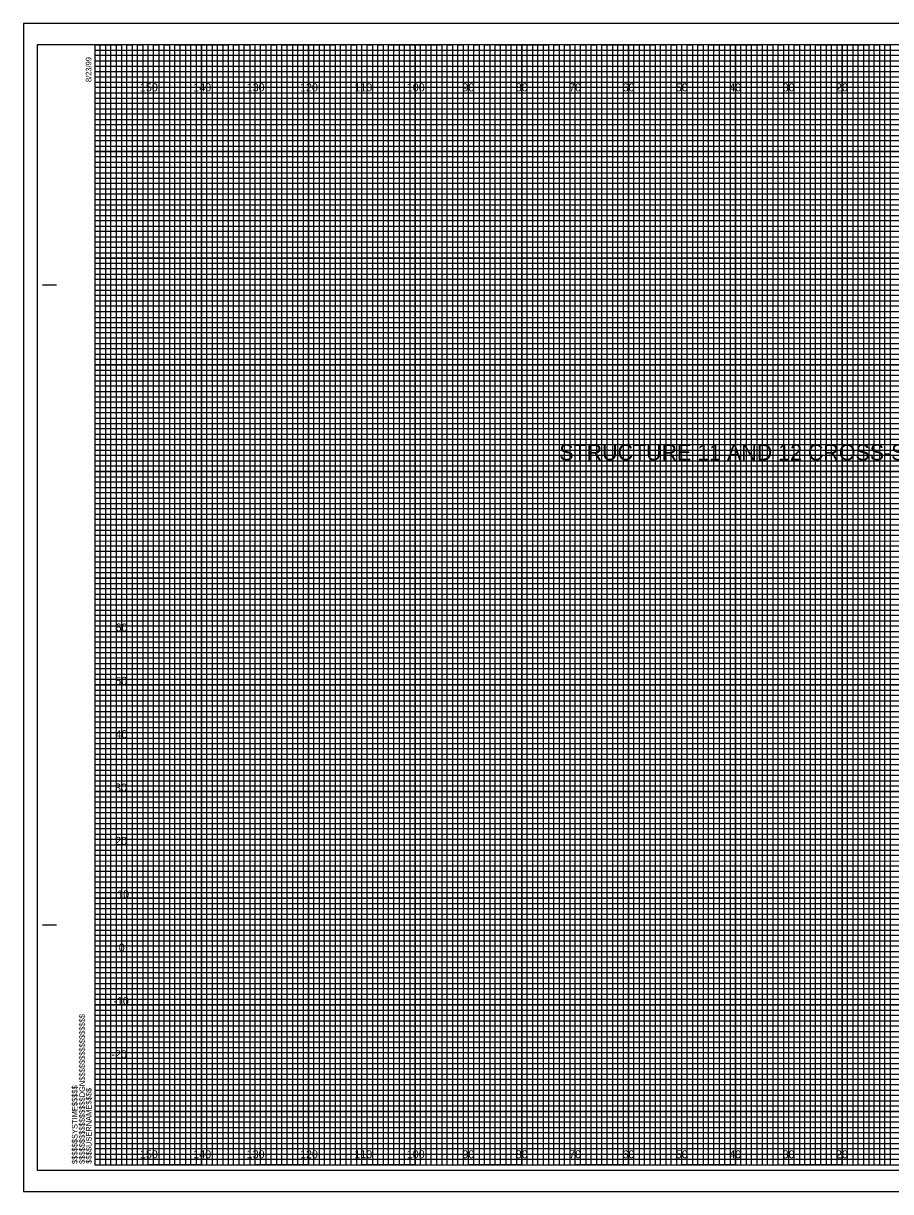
# Model space of a CAD drawing. Extents: x -13 to 886, y -5 to 434.
# Drawn here: x -13.4 to 149.1, y 215 to 434 of the extents above; entities that cross this region are included whole.
import ezdxf

# ---------------------------------------------------------------- set-up
doc = ezdxf.new("R2010")
doc.units = 0
for name, color, linetype in [('Prop Road Sect_ Boring - Header Labels from Geopak', 7, 'Continuous'), ('Prop XS Elevation Labels', 7, 'Continuous'), ('Prop XS Offset Labels', 7, 'Continuous'), ('Sheet Cross Section CELL', 7, 'Continuous'), ('Sheet Cross Section Grid Major CELL', 7, 'Continuous'), ('Sheet Cross Section Grid Middle CELL', 7, 'Continuous'), ('Sheet Cross Section Grid Minor 1 CELL', 7, 'Continuous'), ('Sheet Cross Section Grid Minor 2 CELL', 7, 'Continuous'), ('Sheet Cutting Line CELL', 7, 'Continuous'), ('Sheet DOT Grid CELL', 7, 'Continuous'), ('Sheet Plot Border Inside CELL', 7, 'Continuous'), ('Sheet Plot Border Outside CELL', 7, 'Continuous')]:
    doc.layers.add(name, color=color, linetype=linetype)

msp = doc.modelspace()

# ---------------------------------------------------------------- linework, layer by layer
at = {"layer": 'Sheet Cross Section CELL'}
for p, q in [((-9.8, 385), (-7.3, 385)), ((-9.7, 385), (-7.2, 385)), ((-9.8, 265), (-7.3, 265)), ((-9.7, 265), (-7.2, 265)), ((0, 220), (0, 220)), ((0, 220), (0, 220)), ((0, 220), (0, 220)), ((0, 220), (0, 220)), ((0, 220), (0, 220)), ((0, 220), (0, 220)), ((0, 220), (0, 220))]:
    msp.add_line(p, q, dxfattribs=at)
msp.add_lwpolyline([(320, 430), (0, 430), (0, 220), (320, 220)], close=True, dxfattribs=at)
at = {"layer": 'Sheet Cross Section Grid Major CELL'}
for p, q in [((10, 430), (0, 430)), ((10, 220), (10, 430)), ((30, 430), (20, 430)), ((20, 430), (20, 220)), ((30, 220), (30, 430)), ((50, 430), (40, 430)), ((40, 430), (40, 220)), ((50, 220), (50, 430)), ((70, 430), (60, 430)), ((60, 430), (60, 220)), ((70, 220), (70, 430)), ((90, 430), (80, 430)), ((80, 430), (80, 220)), ((90, 220), (90, 430)), ((110, 430), (100, 430)), ((100, 430), (100, 220)), ((110, 220), (110, 430)), ((130, 430), (120, 430)), ((120, 430), (120, 220)), ((130, 220), (130, 430)), ((150, 430), (140, 430)), ((140, 430), (140, 220)), ((20, 220), (10, 220)), ((40, 220), (30, 220)), ((60, 220), (50, 220)), ((80, 220), (70, 220)), ((100, 220), (90, 220)), ((120, 220), (110, 220)), ((140, 220), (130, 220))]:
    msp.add_line(p, q, dxfattribs=at)
for points in [[(0, 420), (320, 420), (320, 410), (0, 410)], [(0, 400), (320, 400), (320, 390), (0, 390)], [(0, 380), (320, 380), (320, 370), (0, 370)], [(0, 360), (320, 360), (320, 350), (0, 350)], [(0, 340), (320, 340), (320, 330), (0, 330)], [(0, 320), (320, 320), (320, 310), (0, 310)], [(0, 300), (320, 300), (320, 290), (0, 290)], [(0, 280), (320, 280), (320, 270), (0, 270)], [(0, 260), (320, 260), (320, 250), (0, 250)], [(0, 240), (320, 240), (320, 230), (0, 230)]]:
    msp.add_lwpolyline(points, dxfattribs=at)
at = {"layer": 'Sheet Cross Section Grid Middle CELL'}
for points in [[(0, 430), (5, 430), (5, 220), (15, 220), (15, 430), (25, 430), (25, 220), (35, 220), (35, 430), (45, 430), (45, 220), (55, 220), (55, 430), (65, 430), (65, 220), (75, 220), (75, 430), (85, 430), (85, 220), (95, 220), (95, 430), (105, 430), (105, 220), (115, 220), (115, 430), (125, 430), (125, 220), (135, 220), (135, 430), (145, 430), (145, 220), (155, 220)], [(0, 425), (275, 425)], [(0, 405), (320, 405), (320, 415), (0, 415)], [(0, 385), (320, 385), (320, 395), (0, 395)], [(0, 365), (320, 365), (320, 375), (0, 375)], [(0, 345), (320, 345), (320, 355), (0, 355)], [(0, 325), (320, 325), (320, 335), (0, 335)], [(0, 305), (320, 305), (320, 315), (0, 315)], [(0, 285), (320, 285), (320, 295), (0, 295)], [(0, 265), (320, 265), (320, 275), (0, 275)], [(0, 245), (320, 245), (320, 255), (0, 255)], [(0, 225), (320, 225), (320, 235), (0, 235)]]:
    msp.add_lwpolyline(points, dxfattribs=at)
at = {"layer": 'Sheet Cross Section Grid Minor 1 CELL'}
for p, q in [((0, 429), (260, 429)), ((260, 427.98), (0, 427.98)), ((0, 427.98), (0, 427)), ((0, 427), (260, 427)), ((260, 425.89), (0, 425.89)), ((0, 425.89), (0, 424)), ((0, 424), (320, 424))]:
    msp.add_line(p, q, dxfattribs=at)
for points in [[(0, 423), (270, 423), (320, 423), (320, 422), (0, 422)], [(0, 421), (320, 421), (320, 419), (0, 419)], [(0, 418), (320, 418), (320, 417), (0, 416.98)], [(0, 416), (320, 416), (320, 414), (0, 414)], [(0, 413), (320, 413), (320, 412), (0, 412)], [(0, 411), (320, 411), (320, 409), (0, 409)], [(0, 408), (320, 408), (320, 407), (0, 407)], [(0, 406), (320, 406), (320, 404), (0, 404)], [(0, 403), (320, 403), (320, 402), (0, 402)], [(0, 401), (320, 401), (320, 399), (0, 399)], [(0, 398), (320, 398), (320, 397), (0, 397)], [(0, 396), (320, 396), (320, 393.95), (320, 393), (320, 392), (0, 392)], [(0, 394), (320, 394), (320, 393), (0, 393)], [(0, 391), (320, 391), (320, 389), (0, 389.03)], [(0, 389.03), (320, 389), (320, 388), (0, 388)], [(0, 387), (320, 387), (320, 386), (0, 386)], [(0, 384), (320, 384), (320, 383), (0, 383)], [(0, 382), (320, 382), (320, 381), (0, 381)], [(-0.07, 378.89), (320, 378.89), (320, 377.88), (-0.07, 377.88)], [(0, 377), (320, 377), (320, 376), (0, 376)], [(0, 374), (320, 374), (320, 373), (0, 373)], [(0, 372), (320, 372), (320, 371), (0, 371)], [(0, 369), (320, 369), (320, 368), (0, 368)], [(0, 367), (320, 367), (320, 366), (0, 366)], [(0, 364), (320, 364), (320, 363), (0, 363)], [(0, 362), (320, 362), (320, 361), (0, 361)], [(0, 359), (320, 359), (319.99, 357.98), (0, 358)], [(0, 357), (320, 357), (320, 356), (0, 356)], [(0, 354), (320, 354), (320, 353), (0, 353)], [(0, 352), (320, 352), (320, 351), (0, 351)], [(0, 349), (320, 349), (320, 348), (0, 348)], [(0, 347), (320, 347), (320, 346), (0, 346)], [(0, 344), (320, 344), (320, 343), (0, 343)], [(0, 342), (320, 342), (320, 341), (0, 341)], [(0, 339), (320, 339), (320, 338), (0, 338)], [(0, 336.99), (320.07, 336.91), (320, 336), (0, 336)], [(0, 334), (320, 334), (320, 333), (0, 333)], [(0, 332), (320, 332), (320, 331), (0, 331)], [(0, 329), (320, 329), (320, 328), (0, 328)], [(0, 327), (320, 327), (320, 326), (0, 326)], [(0, 324), (320, 324), (320, 323), (0, 323)], [(0, 322), (320, 322), (320, 321), (0, 321)], [(0, 319), (320, 319), (320, 318), (0, 318)], [(0, 317), (320, 317), (320, 316), (0, 316)], [(0, 314), (320, 314), (320, 313), (0, 313)], [(0, 312), (320, 312), (320, 311), (0, 311)], [(0, 309), (320, 309), (320, 308), (0, 308)], [(0, 307), (320, 307), (320, 306), (0, 306)], [(0, 304), (320, 304), (320, 303), (0, 303)], [(0, 302), (320, 302), (320, 301), (0, 301)], [(0, 299), (320, 299), (319.99, 297.98), (0, 298)], [(0, 297), (320, 297), (320, 296), (0, 296)], [(0, 294), (320, 294), (320, 293), (0, 293)], [(0, 292), (320, 292), (320, 291), (0, 291)], [(0, 289), (320, 289), (320, 288), (0, 288)], [(0, 287), (320, 287), (320, 286), (0, 286)], [(0, 284), (320, 284), (320, 283), (0, 283)], [(0, 282), (320, 282), (320, 281), (0, 281)], [(0, 279), (320, 279), (320, 278), (0, 278)], [(0, 276.99), (320.07, 276.91), (320, 276), (0, 276)], [(0, 274), (320, 274), (320, 273), (0, 273)], [(0, 272), (320, 272), (320, 271), (0, 271)], [(0, 269), (320, 269), (320, 268), (0, 268)], [(0, 267), (320, 267), (320, 266), (0, 266)], [(0, 264), (320, 264), (320, 263), (0, 263)], [(0, 262), (320, 262), (320, 261), (0, 261)], [(0, 259), (320, 259), (320, 258), (0, 258)], [(0, 257), (320, 257), (320, 256), (0, 256)], [(0, 254), (320, 254), (320, 253), (0, 253)], [(0, 252), (320, 252), (320, 251), (0, 251)], [(0, 249), (320, 249), (320, 248), (0, 248)], [(0, 247), (320, 247), (320, 246), (0, 246)], [(0, 244), (320, 244), (320, 243), (0, 243)], [(0, 242), (320, 242), (320, 241), (0, 241)], [(0, 239), (320, 239), (320, 238), (0, 238)], [(0, 237), (320, 237), (320, 236), (0, 236)], [(0, 234), (320, 234), (320, 233), (0, 233)], [(0, 232), (320, 232), (320, 231), (0, 231)], [(0, 229), (320, 229), (320, 228), (0, 228)], [(0, 227), (320, 227), (320, 226), (0, 226)], [(0, 224), (320, 224), (320, 223), (0, 223)], [(0, 222), (320, 222), (320, 221), (0, 221)]]:
    msp.add_lwpolyline(points, dxfattribs=at)
at = {"layer": 'Sheet Cross Section Grid Minor 2 CELL'}
for points in [[(0, 220), (1, 220), (1, 430), (2, 430), (2, 220)], [(2, 220), (3, 220), (3, 430), (4, 430), (4, 220)], [(5, 220), (6, 220), (6, 430), (7, 430), (7, 220)], [(7, 220), (8, 220), (8, 430), (9, 430), (9, 220)], [(10, 220), (11, 220), (11, 430), (12, 430), (12, 220)], [(12, 220), (13, 220), (13, 430), (14, 430), (14, 220)], [(15, 220), (16, 220), (16, 430), (17, 430), (17, 220)], [(17, 220), (18, 220), (18, 430), (19, 430), (19, 220)], [(20, 220), (21, 220), (21, 430), (22, 430), (22, 220)], [(22, 220), (23, 220), (23, 430), (24, 430), (24, 220)], [(25, 220), (26, 220), (26, 430), (27, 430), (27, 220)], [(27, 220), (28, 220), (28, 430), (29, 430), (29, 220)], [(30, 220), (31, 220), (31, 430), (32, 430), (32, 220)], [(32, 220), (33, 220), (33, 430), (34, 430), (34, 220)], [(35, 220), (36, 220), (36, 430), (37, 430), (37, 220)], [(37, 220), (38, 220), (38, 430), (39, 430), (39, 220)], [(40, 220), (41, 220), (41, 430), (42, 430), (42, 220)], [(42, 220), (43, 220), (43, 430), (44, 430), (44, 220)], [(45, 220), (46, 220), (46, 430), (47, 430), (47, 220)], [(47, 220), (48, 220), (48, 430), (49, 430), (49, 220)], [(50, 220), (51, 220), (51, 430), (52, 430), (52, 220)], [(52, 220), (53, 220), (53, 430), (54, 430), (54, 220)], [(55, 220), (56, 220), (56, 430), (57, 430), (57, 220)], [(57, 220), (58, 220), (58, 430), (59, 430), (59, 220)], [(60, 220), (61, 220), (61, 430), (62, 430), (62, 220)], [(62, 220), (63, 220), (63, 430), (64, 430), (64, 220)], [(65, 220), (66, 220), (66, 430), (67, 430), (67, 220)], [(67, 220), (68, 220), (68, 430), (69, 430), (69, 220)], [(70, 220), (71, 220), (71, 430), (72, 430), (72, 220)], [(72, 220), (73, 220), (73, 430), (74, 430), (74, 220)], [(75, 220), (76, 220), (76, 430), (77, 430), (77, 220)], [(77, 220), (78, 220), (78, 430), (79, 430), (79, 220)], [(80, 220), (81, 220), (81, 430), (82, 430), (82, 220)], [(82, 220), (83, 220), (83, 430), (84, 430), (84, 220)], [(85, 220), (86, 220), (86, 430), (87, 430), (87, 220)], [(87, 220), (88, 220), (88, 430), (89, 430), (89, 220)], [(90, 220), (91, 220), (91, 430), (92, 430), (92, 220)], [(92, 220), (93, 220), (93, 430), (94, 430), (94, 220)], [(95, 220), (96, 220), (96, 430), (97, 430), (97, 220)], [(97, 220), (98, 220), (98, 430), (99, 430), (99, 220)], [(100, 220), (101, 220), (101, 430), (102, 430), (102, 220)], [(102, 220), (103, 220), (103, 430), (104, 430), (104, 220)], [(105, 220), (106, 220), (106, 430), (107, 430), (107, 220)], [(107, 220), (108, 220), (108, 430), (109, 430), (109, 220)], [(110, 220), (111, 220), (111, 430), (112, 430), (112, 220)], [(112, 220), (113, 220), (113, 430), (114, 430), (114, 220)], [(115, 220), (116, 220), (116, 430), (117, 430), (117, 220)], [(117, 220), (118, 220), (118, 430), (119, 430), (119, 220)], [(120, 220), (121, 220), (121, 430), (122, 430), (122, 220)], [(122, 220), (123, 220), (123, 430), (124, 430), (124, 220)], [(125, 220), (126, 220), (126, 430), (127, 430), (127, 220)], [(127, 220), (128, 220), (128, 430), (129, 430), (129, 220)], [(130, 220), (131, 220), (131, 430), (132, 430), (132, 220)], [(132, 220), (133, 220), (133, 430), (134, 430), (134, 220)], [(135, 220), (136, 220), (136, 430), (137, 430), (137, 220)], [(137, 220), (138, 220), (138, 430), (139, 430), (139, 220)], [(140, 220), (141, 220), (141, 430), (142, 430), (142, 220)], [(142, 220), (143, 220), (143, 430), (144, 430), (144, 220)], [(145, 220), (146, 220), (146, 430), (147, 430), (147, 220)], [(147, 220), (148, 220), (148, 430), (149, 430), (149, 220)]]:
    msp.add_lwpolyline(points, dxfattribs=at)
at = {"layer": 'Sheet Cutting Line CELL'}
for p, q in [((323.3, 434), (-13.4, 434)), ((-13.4, 434), (-13.4, 215)), ((-13.4, 215), (323.3, 215))]:
    msp.add_line(p, q, dxfattribs=at)
at = {"layer": 'Sheet DOT Grid CELL'}
for p, q in [((10, 220), (10, 430)), ((20, 220), (20, 430)), ((30, 220), (30, 430)), ((40, 220), (40, 430)), ((50, 220), (50, 430)), ((60, 220), (60, 430)), ((70, 220), (70, 430)), ((80, 220), (80, 430)), ((90, 220), (90, 430)), ((100, 220), (100, 430)), ((110, 220), (110, 430)), ((120, 220), (120, 430)), ((130, 220), (130, 430)), ((140, 220), (140, 430)), ((0, 420), (320, 420)), ((0, 410), (320, 410)), ((0, 400), (320, 400)), ((0, 390), (320, 390)), ((0, 380), (320, 380)), ((0, 370), (320, 370)), ((0, 360), (320, 360)), ((0, 350), (320, 350)), ((0, 340), (320, 340)), ((0, 330), (320, 330)), ((0, 320), (320, 320)), ((0, 310), (320, 310)), ((0, 300), (320, 300)), ((0, 290), (320, 290)), ((0, 280), (320, 280)), ((0, 270), (320, 270)), ((0, 260), (320, 260)), ((0, 250), (320, 250)), ((0, 240), (320, 240)), ((0, 230), (320, 230))]:
    msp.add_line(p, q, dxfattribs=at)
at = {"layer": 'Sheet Plot Border Inside CELL'}
msp.add_lwpolyline([(-10.8, 219), (322.4, 219), (322.4, 430), (-10.8, 430)], close=True, dxfattribs=at)
at = {"layer": 'Sheet Plot Border Outside CELL'}
msp.add_lwpolyline([(-13.4, 215), (323.3, 215), (323.3, 434), (-13.4, 434)], close=True, dxfattribs=at)

# ---------------------------------------------------------------- texts
at = {"layer": 'Prop Road Sect_ Boring - Header Labels from Geopak'}
msp.add_text('STRUCTURE 11 AND 12 CROSS-SECTION THROUGH END BENT 2', height=3, dxfattribs=at).set_placement((87.01, 352.09))
at = {"layer": 'Prop XS Elevation Labels'}
for s, p in [('60', (3.87, 320)), ('50', (3.82, 310)), ('40', (3.87, 300)), ('30', (3.78, 290)), ('20', (3.8, 280)), ('10', (4.17, 270)), ('0', (4.47, 260)), ('-10', (3.46, 250)), ('-20', (3.09, 240))]:
    msp.add_text(s, height=1.5, dxfattribs=at).set_placement(p)
at = {"layer": 'Prop XS Offset Labels'}
for s, p in [('150', (8.44, 421.25)), ('140', (18.44, 421.25)), ('130', (28.44, 421.25)), ('120', (38.44, 421.25)), ('110', (48.62, 421.25)), ('100', (58.44, 421.25)), ('90', (68.86, 421.25)), ('80', (78.86, 421.25)), ('70', (88.86, 421.25)), ('60', (98.86, 421.25)), ('50', (108.86, 421.25)), ('40', (118.86, 421.25)), ('30', (128.86, 421.25)), ('20', (138.86, 421.25)), ('150', (8.44, 221.25)), ('140', (18.44, 221.25)), ('130', (28.44, 221.25)), ('120', (38.44, 221.25)), ('110', (48.62, 221.25)), ('100', (58.44, 221.25)), ('90', (68.86, 221.25)), ('80', (78.86, 221.25)), ('70', (88.86, 221.25)), ('60', (98.86, 221.25)), ('50', (108.86, 221.25)), ('40', (118.86, 221.25)), ('30', (128.86, 221.25)), ('20', (138.86, 221.25))]:
    msp.add_text(s, height=1.5, dxfattribs=at).set_placement(p)
at = {"layer": 'Sheet Cross Section CELL'}
for s, p in [('8/23/99', (-0.65, 423)), ('$$$$$$$$$$$$$$$$DGN$$$$$$$$$$$$$$$$', (-1.88, 220.18)), ('$$$$$$SYSTIME$$$$$', (-3.26, 220.18)), ('$$$$USERNAME$$$$', (-0.62, 220.23))]:
    msp.add_text(s, height=1.05, rotation=90, dxfattribs=at).set_placement(p)

doc.saveas('drawing.dxf')
